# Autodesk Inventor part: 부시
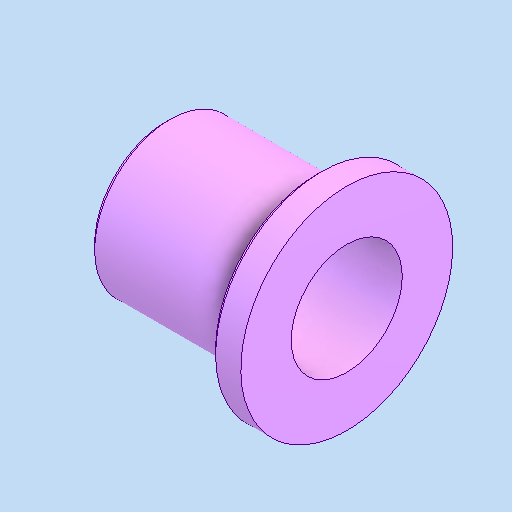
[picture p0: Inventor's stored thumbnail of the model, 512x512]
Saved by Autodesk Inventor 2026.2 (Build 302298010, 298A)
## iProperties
Created: 2026-08
Part Number: 부시
Material: 강철, 연강
Document SubType Name: Modeling
Designer: PC-2-06
Density: 7.86 g/cm^3
Appearance: 기본값
Author: jhkim
Sending System: Autodesk Inventor 2027
Preprocessor: ST-DEVELOPER v20.1
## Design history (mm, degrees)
feature "솔리드1"
node "솔리드2"
